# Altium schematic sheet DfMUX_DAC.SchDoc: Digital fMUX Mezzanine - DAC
size 386 x 246 mm; Engineer: M.Dobbs, McGill U.; Revision: 4
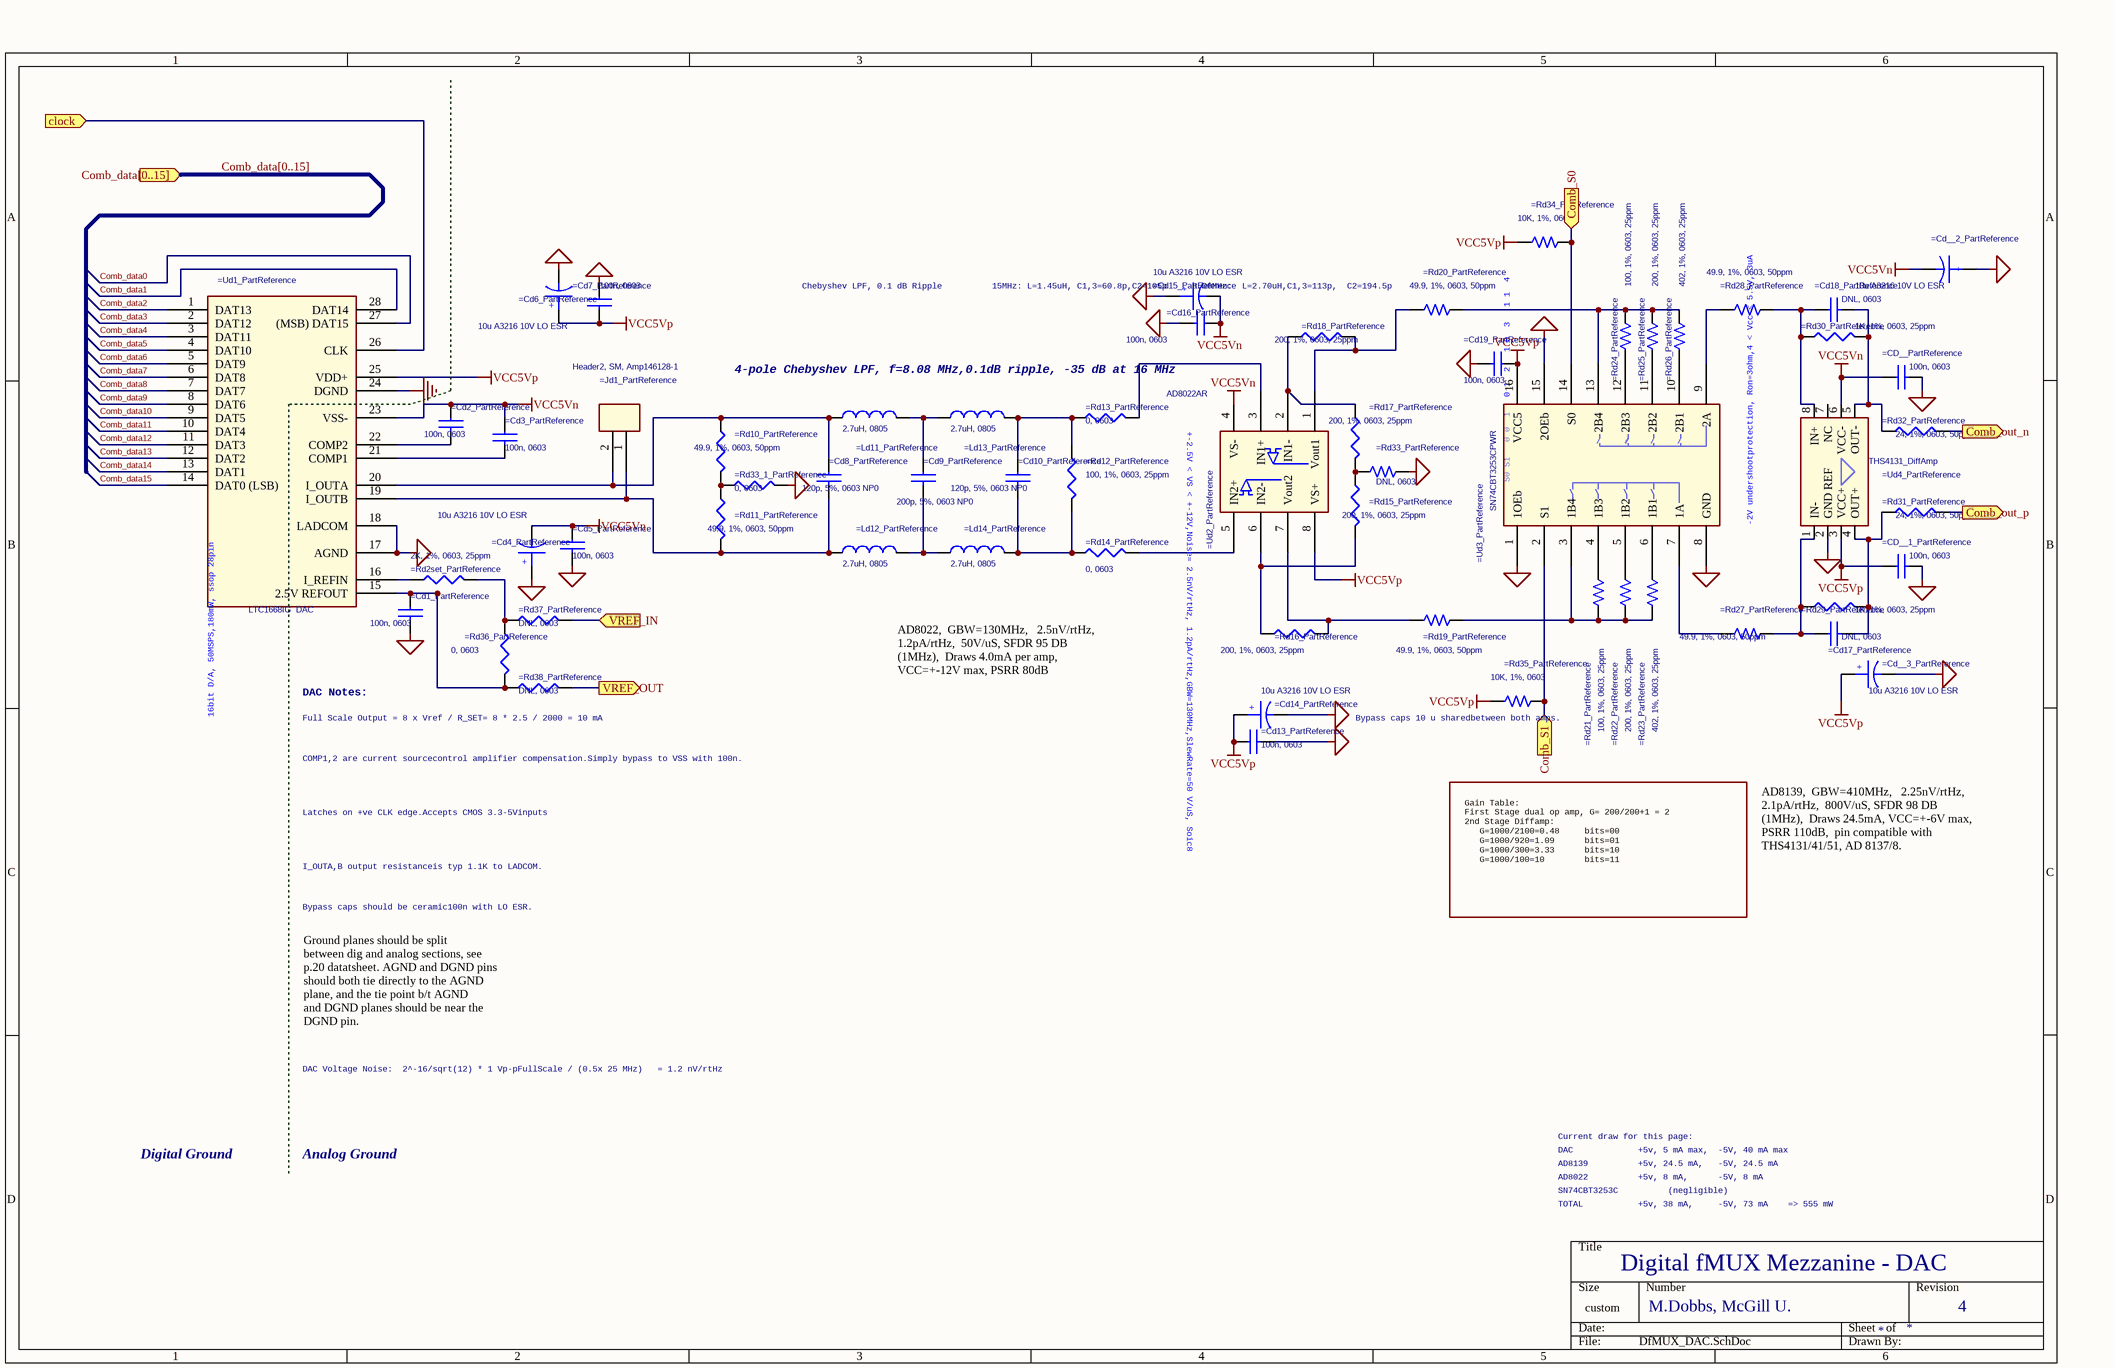
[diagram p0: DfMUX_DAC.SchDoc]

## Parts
=Cd1_PartReference  100n, 0603  [0603c]
=Cd2_PartReference  100n, 0603  [0603c]
=Cd3_PartReference  100n, 0603  [0603c]
=Cd4_PartReference  10u A3216 10V LO ESR  [TANTA]
=Cd5_PartReference  100n, 0603  [0603c]
=Cd6_PartReference  10u A3216 10V LO ESR  [TANTA]
=Cd7_PartReference  100n, 0603  [0603c]
=Cd8_PartReference  120p, 5%, 0603 NP0  [0603c]
=Cd9_PartReference  200p, 5%, 0603 NP0  [0603c]
=Cd10_PartReference  120p, 5%, 0603 NP0  [0603c]
=Cd13_PartReference  100n, 0603  [0603c]
=Cd14_PartReference  10u A3216 10V LO ESR  [TANTA]
=Cd15_PartReference  10u A3216 10V LO ESR  [TANTA]
=Cd16_PartReference  100n, 0603  [0603c]
=Cd17_PartReference  DNL, 0603  [0603c]
=Cd18_PartReference  DNL, 0603  [0603c]
=Cd19_PartReference  100n, 0603  [0603c]
=CD__1_PartReference  100n, 0603  [0603c]
=Cd__2_PartReference  10u A3216 10V LO ESR  [TANTA]
=Cd__3_PartReference  10u A3216 10V LO ESR  [TANTA]
=CD__PartReference  100n, 0603  [0603c]
=Jd1_PartReference  Header2, SM, Amp146128-1  [HEADER_AMP146128]
=Ld11_PartReference  2.7uH, 0805  [0805L]
=Ld12_PartReference  2.7uH, 0805  [0805L]
=Ld13_PartReference  2.7uH, 0805  [0805L]
=Ld14_PartReference  2.7uH, 0805  [0805L]
=Rd2set_PartReference  2K, 1%, 0603, 25ppm  [0603r]
=Rd10_PartReference  49.9, 1%, 0603, 50ppm  [0603r]
=Rd11_PartReference  49.9, 1%, 0603, 50ppm  [0603r]
=Rd12_PartReference  100, 1%, 0603, 25ppm  [0603r]
=Rd13_PartReference  0, 0603  [0603r]
=Rd14_PartReference  0, 0603  [0603r]
=Rd15_PartReference  200, 1%, 0603, 25ppm  [0603r]
=Rd16_PartReference  200, 1%, 0603, 25ppm  [0603r]
=Rd17_PartReference  200, 1%, 0603, 25ppm  [0603r]
=Rd18_PartReference  200, 1%, 0603, 25ppm  [0603r]
=Rd19_PartReference  49.9, 1%, 0603, 50ppm  [RC05]
=Rd20_PartReference  49.9, 1%, 0603, 50ppm  [RC05]
=Rd21_PartReference  100, 1%, 0603, 25ppm  [RC05]
=Rd22_PartReference  200, 1%, 0603, 25ppm  [RC05]
=Rd23_PartReference  402, 1%, 0603, 25ppm  [RC05]
=Rd24_PartReference  100, 1%, 0603, 25ppm  [RC05]
=Rd25_PartReference  200, 1%, 0603, 25ppm  [RC05]
=Rd26_PartReference  402, 1%, 0603, 25ppm  [RC05]
=Rd27_PartReference  49.9, 1%, 0603, 50ppm  [RC05]
=Rd28_PartReference  49.9, 1%, 0603, 50ppm  [RC05]
=Rd29_PartReference  1K, 1%, 0603, 25ppm  [0603r]
=Rd30_PartReference  1K, 1%, 0603, 25ppm  [0603r]
=Rd31_PartReference  24, 1%, 0603, 50ppm  [0603r]
=Rd32_PartReference  24, 1%, 0603, 50ppm  [0603r]
=Rd33_1_PartReference  0, 0603  [0603r]
=Rd33_PartReference  DNL, 0603  [RC05]
=Rd34_PartReference  10K, 1%, 0603  [RC05]
=Rd35_PartReference  10K, 1%, 0603  [RC05]
=Rd36_PartReference  0, 0603  [0603r]
=Rd37_PartReference  DNL, 0603  [0603r]
=Rd38_PartReference  DNL, 0603  [0603r]
=Ud1_PartReference  LTC1668IG  DAC  [ssop28]
=Ud2_PartReference  AD8022AR  [soic8]
=Ud3_PartReference  SN74CBT3253CPWR  [TSSOP16]
=Ud4_PartReference  THS4131_DiffAmp  [SOIC8]

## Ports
clock, Comb_data[0..15], Comb_out_n, Comb_out_p, Comb_S0, Comb_S1, VREF_IN, VREF_OUT

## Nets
GND_DIG: =Ud1_PartReference.24(DGND)
GND_SIGNAL: =Cd1_PartReference.2 =Cd4_PartReference.1 =Cd5_PartReference.2 =Cd6_PartReference.2 =Cd7_PartReference.1 =Cd13_PartReference.2 =Cd14_PartReference.2 =Cd15_PartReference.1 =Cd16_PartReference.2 =Cd19_PartReference.2 =CD__1_PartReference.2 =Cd__2_PartReference.1 =Cd__3_PartReference.2 =CD__PartReference.2 =Rd33_1_PartReference.2 =Rd33_PartReference.2 =Ud1_PartReference.17(AGND) =Ud1_PartReference.18(LADCOM) =Ud3_PartReference.1(1OEb) =Ud3_PartReference.8(GND) =Ud3_PartReference.15(2OEb) =Ud4_PartReference.2(GND_REF)
VCC5Vn: =Cd2_PartReference.1 =Cd3_PartReference.1 =Cd4_PartReference.2 =Cd5_PartReference.1 =Cd15_PartReference.2 =Cd16_PartReference.1 =Cd__2_PartReference.2 =CD__PartReference.1 =Ud1_PartReference.23(VSS-) =Ud2_PartReference.4(VS-) =Ud4_PartReference.6(VCC-)
VCC5Vp: =Cd6_PartReference.1 =Cd7_PartReference.2 =Cd13_PartReference.1 =Cd14_PartReference.1 =Cd19_PartReference.1 =CD__1_PartReference.1 =Cd__3_PartReference.1 =Rd34_PartReference.1 =Rd35_PartReference.1 =Ud1_PartReference.25(VDD+) =Ud2_PartReference.8(VS+) =Ud3_PartReference.16(VCC5) =Ud4_PartReference.3(VCC+)
clock: =Ud1_PartReference.26(CLK) ; port clock
Comb_data0: =Ud1_PartReference.27((MSB)_DAT15)
Comb_data1: =Ud1_PartReference.28(DAT14)
Comb_data2: =Ud1_PartReference.1(DAT13)
Comb_data3: =Ud1_PartReference.2(DAT12)
Comb_data4: =Ud1_PartReference.3(DAT11)
Comb_data5: =Ud1_PartReference.4(DAT10)
Comb_data6: =Ud1_PartReference.5(DAT9)
Comb_data7: =Ud1_PartReference.6(DAT8)
Comb_data8: =Ud1_PartReference.7(DAT7)
Comb_data9: =Ud1_PartReference.8(DAT6)
Comb_data10: =Ud1_PartReference.9(DAT5)
Comb_data11: =Ud1_PartReference.10(DAT4)
Comb_data12: =Ud1_PartReference.11(DAT3)
Comb_data13: =Ud1_PartReference.12(DAT2)
Comb_data14: =Ud1_PartReference.13(DAT1)
Comb_data15: =Ud1_PartReference.14(DAT0_(LSB))
Comb_out_n: =Rd32_PartReference.2 ; port Comb_out_n
Comb_out_p: =Rd31_PartReference.2 ; port Comb_out_p
Comb_S0: =Rd34_PartReference.2 =Ud3_PartReference.14(S0) ; port Comb_S0
Comb_S1: =Rd35_PartReference.2 =Ud3_PartReference.2(S1) ; port Comb_S1
VREF_IN: =Rd37_PartReference.2 ; port VREF_IN
VREF_OUT: =Rd38_PartReference.2 ; port VREF_OUT
Net=Cd1_PartReference_1: =Cd1_PartReference.1 =Rd36_PartReference.2 =Rd38_PartReference.1 =Ud1_PartReference.15(2.5V_REFOUT)
Net=Cd2_PartReference_2: =Cd2_PartReference.2 =Ud1_PartReference.22(COMP2)
Net=Cd3_PartReference_2: =Cd3_PartReference.2 =Ud1_PartReference.21(COMP1)
Net=Cd8_PartReference_1: =Cd8_PartReference.1 =Jd1_PartReference.2 =Ld11_PartReference.1 =Rd10_PartReference.1 =Ud1_PartReference.20(I_OUTA)
Net=Cd8_PartReference_2: =Cd8_PartReference.2 =Jd1_PartReference.1 =Ld12_PartReference.1 =Rd11_PartReference.2 =Ud1_PartReference.19(I_OUTB)
Net=Cd9_PartReference_1: =Cd9_PartReference.1 =Ld11_PartReference.2 =Ld13_PartReference.1
Net=Cd9_PartReference_2: =Cd9_PartReference.2 =Ld12_PartReference.2 =Ld14_PartReference.1
Net=Cd10_PartReference_1: =Cd10_PartReference.1 =Ld13_PartReference.2 =Rd12_PartReference.1 =Rd13_PartReference.1
Net=Cd10_PartReference_2: =Cd10_PartReference.2 =Ld14_PartReference.2 =Rd12_PartReference.2 =Rd14_PartReference.1
Net=Cd17_PartReference_1: =Cd17_PartReference.1 =Rd27_PartReference.2 =Rd29_PartReference.1 =Ud4_PartReference.1(IN-)
Net=Cd17_PartReference_2: =Cd17_PartReference.2 =Rd29_PartReference.2 =Rd31_PartReference.1 =Ud4_PartReference.4(OUT+)
Net=Cd18_PartReference_1: =Cd18_PartReference.1 =Rd28_PartReference.2 =Rd30_PartReference.1 =Ud4_PartReference.8(IN+)
Net=Cd18_PartReference_2: =Cd18_PartReference.2 =Rd30_PartReference.2 =Rd32_PartReference.1 =Ud4_PartReference.5(OUT-)
Net=Rd2set_PartReference_1: =Rd2set_PartReference.1 =Ud1_PartReference.16(I_REFIN)
Net=Rd2set_PartReference_2: =Rd2set_PartReference.2 =Rd36_PartReference.1 =Rd37_PartReference.1
Net=Rd10_PartReference_2: =Rd10_PartReference.2 =Rd11_PartReference.1 =Rd33_1_PartReference.1
Net=Rd13_PartReference_2: =Rd13_PartReference.2 =Ud2_PartReference.3(IN1+)
Net=Rd14_PartReference_2: =Rd14_PartReference.2 =Ud2_PartReference.5(IN2+)
Net=Rd15_PartReference_1: =Rd15_PartReference.1 =Rd17_PartReference.2 =Rd33_PartReference.1
Net=Rd15_PartReference_2: =Rd15_PartReference.2 =Rd16_PartReference.1 =Ud2_PartReference.6(IN2-)
Net=Rd16_PartReference_2: =Rd16_PartReference.2 =Rd19_PartReference.1 =Ud2_PartReference.7(Vout2)
Net=Rd17_PartReference_1: =Rd17_PartReference.1 =Rd18_PartReference.1 =Ud2_PartReference.2(IN1-)
Net=Rd18_PartReference_2: =Rd18_PartReference.2 =Rd20_PartReference.1 =Ud2_PartReference.1(Vout1)
Net=Rd19_PartReference_2: =Rd19_PartReference.2 =Rd21_PartReference.1 =Rd22_PartReference.1 =Rd23_PartReference.1 =Ud3_PartReference.3(1B4)
Net=Rd20_PartReference_2: =Rd20_PartReference.2 =Rd24_PartReference.2 =Rd25_PartReference.2 =Rd26_PartReference.2 =Ud3_PartReference.13(2B4)
Net=Rd21_PartReference_2: =Rd21_PartReference.2 =Ud3_PartReference.4(1B3)
Net=Rd22_PartReference_2: =Rd22_PartReference.2 =Ud3_PartReference.5(1B2)
Net=Rd23_PartReference_2: =Rd23_PartReference.2 =Ud3_PartReference.6(1B1)
Net=Rd24_PartReference_1: =Rd24_PartReference.1 =Ud3_PartReference.12(2B3)
Net=Rd25_PartReference_1: =Rd25_PartReference.1 =Ud3_PartReference.11(2B2)
Net=Rd26_PartReference_1: =Rd26_PartReference.1 =Ud3_PartReference.10(2B1)
Net=Rd27_PartReference_1: =Rd27_PartReference.1 =Ud3_PartReference.7(1A)
Net=Rd28_PartReference_1: =Rd28_PartReference.1 =Ud3_PartReference.9(2A)

Not connected (* = marked no-connect by the designer): =Ud4_PartReference 7(NC)

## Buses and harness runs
bus Comb_data[0..15] = port Comb_data[0..15]

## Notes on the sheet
- (near =Cd15_PartReference) Chebyshev LPF, 0.1 dB Ripple          15MHz: L=1.45uH, C1,3=60.8p,C2=105p     8.08MHz:  L=2.70uH,C1,3=113p,  C2=194.5p
- 4-pole Chebyshev LPF, f=8.08 MHz,0.1dB ripple, -35 dB at 16 MHz
- DAC Notes:
- Full Scale Output = 8 x Vref / R_SET= 8 * 2.5 / 2000 = 10 mA
- COMP1,2 are current sourcecontrol amplifier compensation.Simply bypass to VSS with 100n.
- AD8022,  GBW=130MHz,   2.5nV/rtHz,
  1.2pA/rtHz,  50V/uS, SFDR 95 DB
  (1MHz),  Draws 4.0mA per amp,
  VCC=+-12V max, PSRR 80dB
- (near =Rd35_PartReference) Bypass caps 10 u sharedbetween both amps.
- Latches on +ve CLK edge.Accepts CMOS 3.3-5Vinputs
- I_OUTA,B output resistanceis typ 1.1K to LADCOM.
- Bypass caps should be ceramic100n with LO ESR.
- Gain Table:
  First Stage dual op amp, G= 200/200+1 = 2
  2nd Stage Diffamp:
  G=1000/2100=0.48     bits=00
  G=1000/920=1.09      bits=01
  G=1000/300=3.33      bits=10
  G=1000/100=10        bits=11
- AD8139,  GBW=410MHz,   2.25nV/rtHz,
  2.1pA/rtHz,  800V/uS, SFDR 98 DB
  (1MHz),  Draws 24.5mA, VCC=+-6V max,
  PSRR 110dB,  pin compatible with
  THS4131/41/51, AD 8137/8.
- Ground planes should be split
  between dig and analog sections, see
  p.20 datatsheet. AGND and DGND pins
  should both tie directly to the AGND
  plane, and the tie point b/t AGND
  and DGND planes should be near the
  DGND pin.
- DAC Voltage Noise:  2^-16/sqrt(12) * 1 Vp-pFullScale / (0.5x 25 MHz)   = 1.2 nV/rtHz
- Digital Ground
- Analog Ground
- Current draw for this page:
- DAC             +5v, 5 mA max,  -5V, 40 mA max
- AD8139          +5v, 24.5 mA,   -5V, 24.5 mA
- AD8022          +5v, 8 mA,      -5V, 8 mA
- SN74CBT3253C          (negligible)
- TOTAL           +5v, 38 mA,     -5V, 73 mA    => 555 mW

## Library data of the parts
=Cd1_PartReference =Cd2_PartReference =Cd3_PartReference =Cd8_PartReference =Cd9_PartReference =Cd10_PartReference =Cd18_PartReference = CAPACITOR NON-POL: COMPFIXED: NO; COMPGROUP: 0; COMPHEIGHT: 0.000; COMPROT: 270; COMPSIDE: TOP
=Cd4_PartReference =Cd__2_PartReference = CAPACITOR POL: COMPFIXED: NO; COMPGROUP: 0; COMPHEIGHT: 0.000; COMPROT: 180; COMPSIDE: BOT
=Cd5_PartReference = CAPACITOR NON-POL: COMPFIXED: NO; COMPGROUP: 0; COMPHEIGHT: 0.000; COMPSIDE: BOT
=Cd6_PartReference =Cd14_PartReference = CAPACITOR POL: COMPFIXED: NO; COMPGROUP: 0; COMPHEIGHT: 0.000; COMPSIDE: BOT
=Cd7_PartReference = CAPACITOR NON-POL: COMPFIXED: NO; COMPGROUP: 0; COMPHEIGHT: 0.000; COMPROT: 180; COMPSIDE: BOT
=Cd13_PartReference =Cd16_PartReference =CD__1_PartReference =CD__PartReference = CAPACITOR NON-POL: COMPFIXED: NO; COMPGROUP: 0; COMPHEIGHT: 0.000; COMPSIDE: TOP
=Cd15_PartReference = CAPACITOR POL: COMPFIXED: NO; COMPGROUP: 0; COMPHEIGHT: 0.000; COMPSIDE: TOP
=Cd17_PartReference = CAPACITOR NON-POL: COMPFIXED: NO; COMPGROUP: 0; COMPHEIGHT: 0.000; COMPROT: 90; COMPSIDE: TOP
=Cd19_PartReference = CAPACITOR NON-POL: COMPFIXED: NO; COMPGROUP: 0; COMPHEIGHT: 0.000; COMPROT: 180; COMPSIDE: TOP
=Cd__3_PartReference = CAPACITOR POL: COMPFIXED: NO; COMPGROUP: 0; COMPHEIGHT: 0.000; COMPROT: 180; COMPSIDE: BOT; FPLIST: 0603c
=Jd1_PartReference = CONN_TRBLK_2: COMPFIXED: NO; COMPGROUP: 0; COMPHEIGHT: 0.000; COMPROT: 90; COMPSIDE: TOP; FPLIST: 0805L
=Ld11_PartReference =Ld12_PartReference =Ld13_PartReference =Ld14_PartReference = INDUCTOR/SM: COMPFIXED: NO; COMPGROUP: 0; COMPHEIGHT: 0.000; COMPSIDE: TOP
=Rd2set_PartReference =Rd13_PartReference =Rd14_PartReference =Rd16_PartReference =Rd17_PartReference =Rd18_PartReference =Rd31_PartReference =Rd32_PartReference =Rd37_PartReference =Rd38_PartReference = R_Dup1: COMPFIXED: NO; COMPGROUP: 0; COMPHEIGHT: 0.000; COMPSIDE: TOP
=Rd10_PartReference =Rd29_PartReference = R_Dup1: COMPFIXED: NO; COMPGROUP: 0; COMPHEIGHT: 0.000; COMPROT: 90; COMPSIDE: TOP
=Rd11_PartReference =Rd12_PartReference =Rd30_PartReference = R_Dup1: COMPFIXED: NO; COMPGROUP: 0; COMPHEIGHT: 0.000; COMPROT: 270; COMPSIDE: TOP
=Rd15_PartReference =Rd33_1_PartReference =Rd36_PartReference = R_Dup1: COMPFIXED: NO; COMPGROUP: 0; COMPHEIGHT: 0.000; COMPROT: 180; COMPSIDE: TOP
=Rd19_PartReference =Rd20_PartReference =Rd21_PartReference =Rd22_PartReference =Rd23_PartReference =Rd27_PartReference =Rd28_PartReference = R_Dup2: PSpiceTemplate: R^@REFDES %1 %2 ?TOLERANCE|R^@REFDES| @VALUE  ?TOLERANCE|\n.model R^@REFDES RES R=1 DEV=@TOLERANCE%|; COMPFIXED: NO; COMPGROUP: 0; COMPHEIGHT: 0.000; COMPSIDE: TOP
=Rd24_PartReference =Rd25_PartReference =Rd26_PartReference =Rd33_PartReference =Rd34_PartReference =Rd35_PartReference = R_Dup2: PSpiceTemplate: R^@REFDES %1 %2 ?TOLERANCE|R^@REFDES| @VALUE  ?TOLERANCE|\n.model R^@REFDES RES R=1 DEV=@TOLERANCE%|; COMPFIXED: NO; COMPGROUP: 0; COMPHEIGHT: 0.000; COMPROT: 180; COMPSIDE: TOP
=Ud1_PartReference = LTC1668IG  DAC: COMPFIXED: NO; COMPGROUP: 0; COMPHEIGHT: 0.000; COMPROT: 270; COMPSIDE: TOP
=Ud2_PartReference = AD8022AR_0: COMPFIXED: NO; COMPGROUP: 0; COMPHEIGHT: 0.000; COMPROT: 180; COMPSIDE: TOP
=Ud3_PartReference = SN74CBT3253C 4MUX: COMPFIXED: NO; COMPGROUP: 0; COMPHEIGHT: 0.000; COMPSIDE: TOP
=Ud4_PartReference = THS4131_DiffAmp_0: COMPFIXED: NO; COMPGROUP: 0; COMPHEIGHT: 0.000; COMPSIDE: TOP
